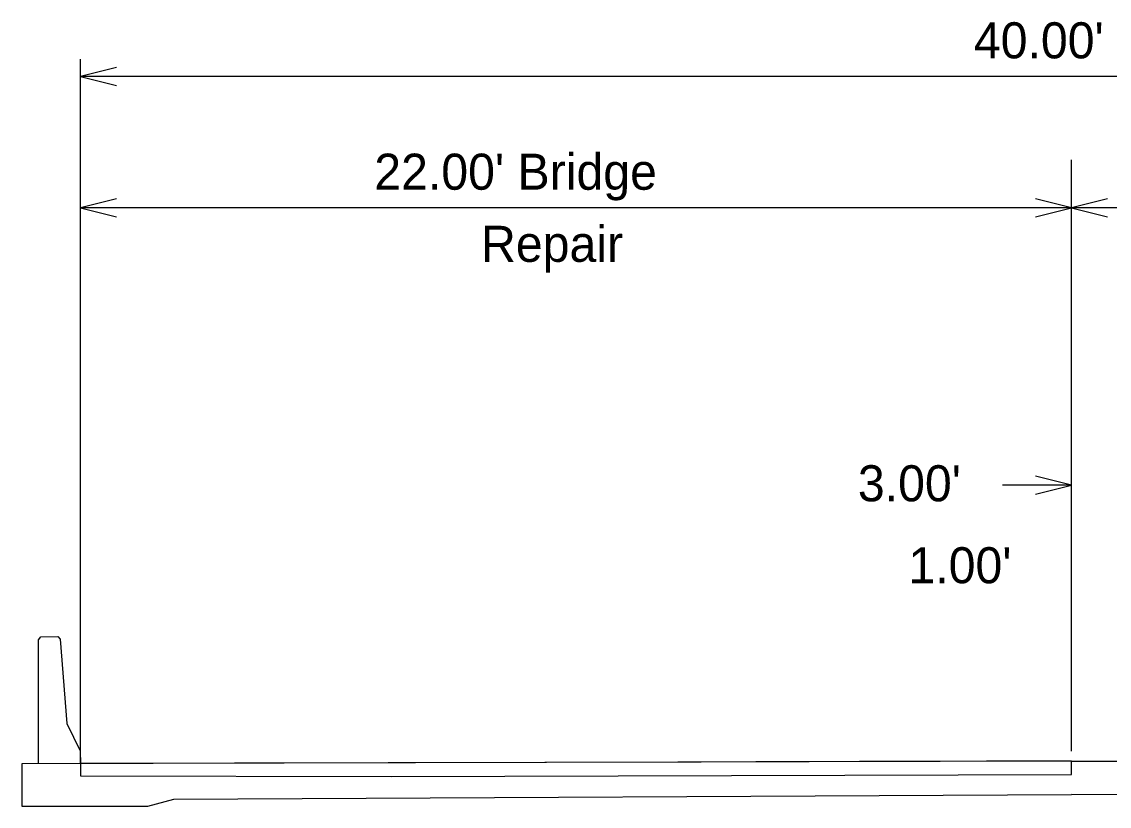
# Model space of a CAD drawing. Extents: x 8410 to 81668, y 7924 to 12712.
# Drawn here: x 14588 to 15273, y 11385 to 11879 of the extents above; entities that cross this region are included whole.
import ezdxf

# ---------------------------------------------------------------- set-up
doc = ezdxf.new("R2010")
doc.units = 0
doc.layers.add('Level 2', color=7, linetype='Continuous')
doc.layers.add('Level 3', color=7, linetype='Continuous')

msp = doc.modelspace()

# ---------------------------------------------------------------- linework, layer by layer
at = {"layer": 'Level 2'}
for p, q in [((14624.81, 11412.03), (14624.81, 11855.65)), ((15873.4, 11844.73), (14624.81, 11844.73)), ((15249.1, 11419.82), (15249.1, 11792.18)), ((15249.1, 11762.02), (14624.81, 11762.02)), ((15873.4, 11762.02), (15249.1, 11762.02)), ((15249.1, 11587.37), (15205.66, 11587.37)), ((14598.46, 11490.01), (14599.82, 11491.9)), ((14598.46, 11411.97), (14598.46, 11490.01)), ((14599.82, 11491.9), (14610.65, 11492.15)), ((14610.65, 11492.15), (14612.05, 11490.32)), ((14612.05, 11490.32), (14616.22, 11437.28)), ((14616.22, 11437.28), (14624.73, 11419.98)), ((14624.73, 11419.98), (14624.81, 11412.03)), ((14683.59, 11389.63), (15249.1, 11392.55)), ((15814.62, 11389.63), (15249.1, 11392.55)), ((14667.37, 11385.19), (14683.59, 11389.63))]:
    msp.add_line(p, q, dxfattribs=at)
for points in [[(14647.52, 11850.41), (14624.81, 11844.73), (14647.52, 11839.05)], [(14647.52, 11767.7), (14624.81, 11762.02), (14647.52, 11756.34)], [(15226.4, 11756.34), (15249.1, 11762.02), (15226.4, 11767.7)], [(15271.81, 11767.7), (15249.1, 11762.02), (15271.81, 11756.34)], [(15226.4, 11581.7), (15249.1, 11587.37), (15226.4, 11593.05)], [(14587.89, 11411.94), (14587.89, 11385.19), (14667.37, 11385.19)]]:
    msp.add_lwpolyline(points, dxfattribs=at)
at = {"layer": 'Level 3'}
for p, q in [((15249.1, 11413.66), (14587.89, 11411.94)), ((15249.1, 11413.66), (15910.32, 11411.94)), ((14820.79, 11403.94), (15249.1, 11405.24)), ((15249.1, 11405.24), (15249.1, 11409.85))]:
    msp.add_line(p, q, dxfattribs=at)
for points in [[(14818.62, 11412.56), (14624.81, 11412.03), (14624.84, 11404.35), (14820.79, 11403.94)], [(15249.1, 11409.85), (15249.1, 11413.66), (15239.94, 11413.58), (15221.42, 11413.54), (15195.42, 11413.48), (15162.68, 11413.4), (15115.51, 11413.28), (15050.26, 11413.12), (15015.81, 11413.04), (14818.62, 11412.56)]]:
    msp.add_lwpolyline(points, dxfattribs=at)

# ---------------------------------------------------------------- texts
at = {"layer": 'Level 2'}
for s, height, p in [("40.00'", 22.709, (15187.55, 11856.09)), ("22.00' Bridge", 22.7091, (14809.91, 11773.37)), ('Repair', 22.709, (14877.15, 11727.96)), ("3.00'", 22.709, (15114.5, 11577.19)), ("1.00'", 22.709, (15146.35, 11525.59))]:
    msp.add_text(s, height=height, dxfattribs=at).set_placement(p)

doc.saveas('drawing.dxf')
